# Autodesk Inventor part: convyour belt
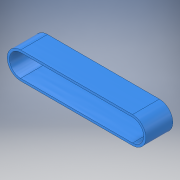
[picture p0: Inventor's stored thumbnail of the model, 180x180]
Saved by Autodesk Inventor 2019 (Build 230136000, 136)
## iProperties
Created: 2021-07
Part Number: convyour belt
Material: Generic
Document SubType Name: Modeling
Designer: Avinash
Density: 1 g/cm^3
Appearance: Cyan
Author: Avinash
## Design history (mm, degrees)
sketch "Sketch2"
  geometry: L1 (0, 0)-(250, 0); L2 (0, -25)-(250, -25); L3 (250, 25)-(0, 25); L4 (0, 30)-(250, 30); L5 (250, -30)-(0, -30); A1 r 25 centre (0, 0) between (0, 25) and (0, -25); A2 r 25 centre (250, 0) between (250, -25) and (250, 25); A3 r 30 centre (250, 0) between (250, -30) and (250, 30); A4 r 30 centre (0, 0) between (0, 30) and (0, -30); 1 further point
  constraints: 12 end point, 8 point on circle, 4 centre point, 4 tangent, 1 horizontal, 1 midpoint, 1 parallel
  dimensions: "d1" = 250 distance of L1.start L1.end; "d2" = 50 diameter of A2
extrude "Extrusion6" new body sketch "Sketch2" stored distance "d30" = 60; taper "d31" = 0 deg
body "Solid5"
